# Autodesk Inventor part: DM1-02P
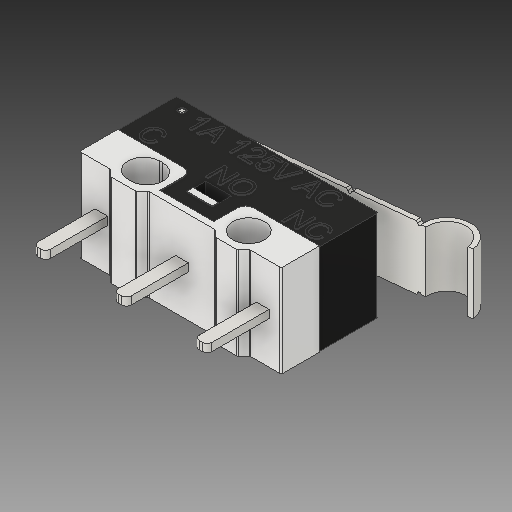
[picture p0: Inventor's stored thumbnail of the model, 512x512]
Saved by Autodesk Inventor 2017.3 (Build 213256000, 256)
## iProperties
Created: 2019-10
Part Number: DM1-02P
Material: Générique
Document SubType Name: Modeling
Designer: ficho
Density: 1 g/cm^3
Appearance: Par défaut
Title: F:\Google Drive\Workspaces\Inventor\Components lib\Switches\Limit switch DM1-02P\DM1-02P.stp
Author: workuser
Sending System: Autodesk Inventor 2019
Preprocessor: ST-DEVELOPER v17
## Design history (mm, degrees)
feature "Solid1"
node "Solide1"
